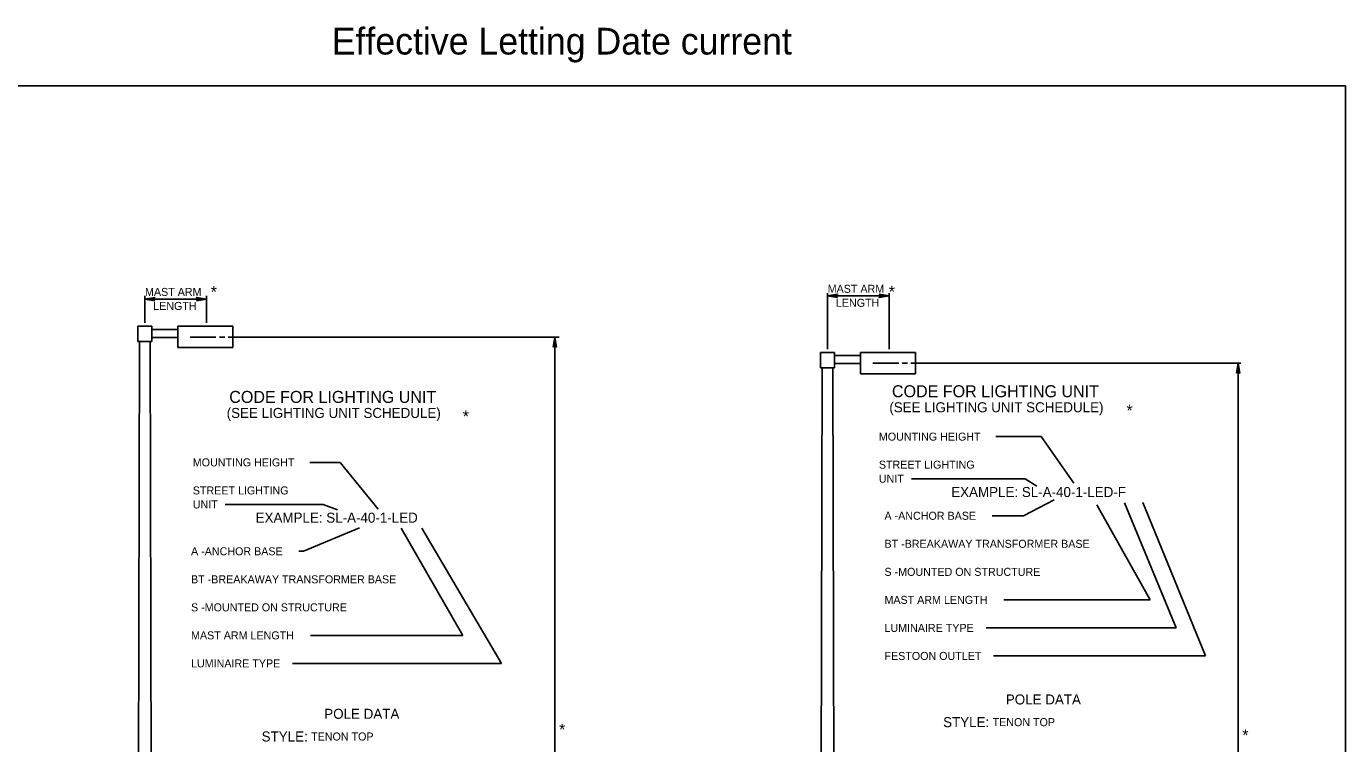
# Model space of a CAD drawing. Extents: x 98556 to 118479, y 99796 to 102182.
# Drawn here: x 106301 to 108279, y 101108 to 102182 of the extents above; entities that cross this region are included whole.
import ezdxf

# ---------------------------------------------------------------- set-up
doc = ezdxf.new("R2010")
doc.units = 0
for name, color, linetype in [('Border Engr Stamp', 7, 'Continuous'), ('Border Organizer Shape', 7, 'Continuous'), ('Default', 7, 'Continuous')]:
    doc.layers.add(name, color=color, linetype=linetype)

msp = doc.modelspace()

# ---------------------------------------------------------------- linework, layer by layer
at = {"layer": 'Border Organizer Shape'}
for p, q in [((106478.7, 101778.6), (106478.7, 101737.8)), ((106571, 101778.6), (106571, 101737.8)), ((107502.1, 101782.3), (107502.1, 101698.6)), ((107594.4, 101778.3), (107502.1, 101778.3)), ((107594.4, 101782.3), (107594.4, 101698.6)), ((106571, 101773.6), (106478.7, 101773.6)), ((106468.2, 101732.8), (106489.1, 101732.8)), ((106468.2, 101709.8), (106468.2, 101732.8)), ((106489.1, 101709.8), (106489.1, 101732.8)), ((106528.4, 101728.2), (106489.1, 101728.2)), ((106528.4, 101700.8), (106528.4, 101732.8)), ((106610.4, 101732.8), (106528.4, 101732.8)), ((106610.4, 101700.8), (106610.4, 101732.8)), ((106470.7, 101709.8), (106467.4, 100412.5)), ((106468.2, 101709.8), (106489.1, 101709.8)), ((106486.7, 101709.8), (106490.1, 100412.7)), ((106528.4, 101716.2), (106489.1, 101716.2)), ((106610.4, 101700.8), (106528.4, 101700.8)), ((106585.4, 101716.6), (106546.8, 101716.6)), ((106598.5, 101716.6), (106590.5, 101716.6)), ((107099.6, 101716.6), (106603.7, 101716.6)), ((107093.3, 101716.6), (107093.3, 100355.6)), ((107491.5, 101693.6), (107512.4, 101693.6)), ((107491.5, 101670.6), (107491.5, 101693.6)), ((107512.4, 101670.6), (107512.4, 101693.6)), ((107551.7, 101689), (107512.4, 101689)), ((107633.7, 101693.6), (107551.7, 101693.6)), ((107551.7, 101661.6), (107551.7, 101693.6)), ((107633.7, 101661.6), (107633.7, 101693.6)), ((107494.1, 101670.6), (107490.7, 100434.7)), ((107491.5, 101670.6), (107512.4, 101670.6)), ((107510.1, 101670.6), (107513.4, 100434.9)), ((107551.7, 101677), (107512.4, 101677)), ((107633.7, 101661.6), (107551.7, 101661.6)), ((107608.7, 101677.4), (107570.1, 101677.4)), ((107621.9, 101677.4), (107613.8, 101677.4)), ((108121.4, 101677.4), (107627, 101677.4)), ((108117.4, 101677.4), (108117.4, 100377.8)), ((107754.4, 101567.5), (107822.3, 101567.5)), ((107822.3, 101567.5), (107871.1, 101497.8)), ((106726, 101528.9), (106771.4, 101528.9)), ((106771.4, 101528.9), (106828.5, 101459)), ((107627.7, 101504.5), (107798.1, 101504.5)), ((107798.1, 101504.5), (107815.9, 101493.3)), ((106599.3, 101465.9), (106746.2, 101465.9)), ((106746.2, 101465.9), (106767.6, 101457.9)), ((107796, 101448.9), (107841.6, 101472.6)), ((107905.6, 101465.3), (107985.4, 101322.9)), ((108024.5, 101280.9), (107947.3, 101468.5)), ((108068.7, 101238.9), (107974.9, 101468.6)), ((107748.8, 101448.9), (107796, 101448.9)), ((106716.7, 101395.7), (106800.5, 101431)), ((106955.4, 101269.7), (106862.9, 101430.5)), ((107013.5, 101227.7), (106894.1, 101430.2)), ((106709.5, 101395.7), (106716.7, 101395.7)), ((107766.5, 101322.9), (107985.4, 101322.9)), ((106727.2, 101269.7), (106955.4, 101269.7)), ((107739.6, 101280.9), (108024.5, 101280.9)), ((106700.3, 101227.7), (107013.5, 101227.7)), ((107750.9, 101238.9), (108068.7, 101238.9))]:
    msp.add_line(p, q, dxfattribs=at)
for points in [[(107517, 101775.7), (107502.1, 101778.3), (107517, 101780.8), (107514.6, 101778.3)], [(107579.4, 101780.8), (107594.4, 101778.3), (107579.4, 101775.7), (107581.8, 101778.3)], [(106493.6, 101771.1), (106478.7, 101773.6), (106493.6, 101776.1), (106491.3, 101773.6)], [(106556.1, 101771.1), (106571, 101773.6), (106556.1, 101776.1), (106558.5, 101773.6)], [(107090.8, 101701.7), (107093.3, 101716.6), (107095.9, 101701.7), (107093.3, 101704.1)], [(108114.9, 101662.5), (108117.4, 101677.4), (108119.9, 101662.5), (108117.4, 101664.9)]]:
    msp.add_lwpolyline(points, close=True, dxfattribs=at)
at = {"layer": 'Default'}
msp.add_lwpolyline([(105078.9, 102093), (108278.6, 102093), (108278.6, 99893.4), (105078.9, 99893.4)], close=True, dxfattribs=at)

# ---------------------------------------------------------------- texts
at = {"layer": 'Border Engr Stamp'}
msp.add_text('Effective Letting Date current', height=40, dxfattribs=at).set_placement((106758.8, 102140))
at = {"layer": 'Border Organizer Shape'}
for s, height, p in [('MAST ARM', 12, (106479, 101778.3)), (' *', 18, (106570.8, 101775.3)), ('MAST ARM', 12, (107502.3, 101783)), (' *', 18, (107587.1, 101775.6)), ('LENGTH', 12, (106491.3, 101757.3)), ('LENGTH', 12, (107514.6, 101762)), ('CODE FOR LIGHTING UNIT', 18, (107598.6, 101626.5)), ('CODE FOR LIGHTING UNIT', 18, (106605.3, 101618)), ('(SEE LIGHTING UNIT SCHEDULE)', 15, (107594.7, 101604)), ('(SEE LIGHTING UNIT SCHEDULE)', 15, (106601.4, 101595.5)), (' *', 18, (106948.5, 101588.8)), (' *', 18, (107943.5, 101597.6)), ('MOUNTING HEIGHT ', 12, (107579, 101561.5)), ('MOUNTING HEIGHT ', 12, (106550.6, 101522.9)), ('STREET LIGHTING ', 12, (107579, 101519.5)), ('UNIT ', 12, (107579, 101498.5)), ('STREET LIGHTING ', 12, (106550.6, 101480.9)), ('EXAMPLE: SL-A-40-1-LED-F', 15, (107687.4, 101477)), ('UNIT ', 12, (106550.6, 101459.9)), ('EXAMPLE: SL-A-40-1-LED', 15, (106644.8, 101438.6)), ('A -ANCHOR BASE ', 12, (107587.4, 101442.9)), ('BT -BREAKAWAY TRANSFORMER BASE', 12, (107587.4, 101400.9)), ('A -ANCHOR BASE ', 12, (106548, 101389.7)), ('S -MOUNTED ON STRUCTURE', 12, (107587.4, 101358.9)), ('BT -BREAKAWAY TRANSFORMER BASE', 12, (106548, 101347.7)), ('MAST ARM LENGTH ', 12, (107587.4, 101316.9)), ('S -MOUNTED ON STRUCTURE', 12, (106548, 101305.7)), ('LUMINAIRE TYPE ', 12, (107587.4, 101274.9)), ('MAST ARM LENGTH ', 12, (106548, 101263.7)), ('FESTOON OUTLET ', 12, (107587.4, 101232.9)), ('LUMINAIRE TYPE ', 12, (106548, 101221.7)), ('POLE DATA', 15, (107769.3, 101166.2)), ('POLE DATA', 15, (106747.7, 101144.7)), ('STYLE:', 15, (107675.3, 101132.2)), (' TENON TOP', 12, (107745, 101133.7)), ('STYLE:', 15, (106653.8, 101110.7)), ('*', 18, (107099.6, 101119.6)), ('*', 18, (108123.7, 101111.1)), (' TENON TOP', 12, (106723.5, 101112.2))]:
    msp.add_text(s, height=height, dxfattribs=at).set_placement(p)

doc.saveas('drawing.dxf')
